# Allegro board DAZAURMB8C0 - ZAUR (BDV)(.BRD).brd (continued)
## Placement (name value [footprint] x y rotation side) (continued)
L5  **MS@HCB2012KF-220T60  [R0805]  209.61 28.18 0 top
L6  BLM15AG121SN1D  [R0402]  184.72 19.42 180 top
L7  BLM15AG121SN1D  [R0402]  184.72 18.27 0 top
L8  *MS@BLM15AG601SN1D  [R0402]  39.69 116.45 0 bottom
L9  *MS@BLM15AG601SN1D  [R0402]  39.61 115.25 0 bottom
L10  **MS@PBY160808T-600Y-N  [R0603]  195.69 24.09 90 bottom
L11  HCB1005KF-330T30  [R0402]  72.22 23.35 90 bottom
L12  HCB1005KF-330T30  [R0402]  75.5 23.99 90 bottom
L13  HCB1608KF-121T30  [R0603]  204.28 19.54 270 bottom
L14  PBY160808T-600Y-N  [R0603]  201.64 18.15 180 bottom
NOREF  -  [unnamed]  12.38 3.42 0 top
NOREF#2  -  [unnamed]  134.02 124.57 0 top
NOREF#3  -  [unnamed]  216.6 44.31 0 top
NOREF#4  -  [#2]  5.68 -31.69 0 top
NOREF#5  -  [#2]  138.82 46.03 0 top
NOREF#6  -  [#2]  165.2 -14.93 0 top
NOREF#7  -  [unnamed]  134.43 121.14 180 bottom
NOREF#8  -  [#2]  145.65 98.38 180 bottom
NOREF#9  -  [unnamed]  10.86 9 180 bottom
NOREF#10  -  [unnamed]  180.78 11.92 180 bottom
PC1  0.1u/25V_4  [C0402]  68.7 125.09 270 top
PC2  1u/10V_4  [C0402]  65.7 125.08 90 top
PC3  10u/10V_4  [C0402_2]  66.77 125.08 270 top
PC4  *22U/6.3V_6  [C0603]  60.86 124.64 90 top
PC5  22u/6.3V_6  [C0603]  61.99 122.62 0 top
PC6  10u/25V_6  [C0603]  69.87 122.24 270 top
PC7  10u/25V_6  [C0603]  71.29 122.14 270 top
PC8  10u/25V_6  [C0603]  72.59 124.61 0 top
PC9  *22U/6.3V_6  [C0603]  49.55 122.11 0 top
PC10  0.047u/50V_6  [C0603]  42.1 122.03 0 top
PC11  0.1u/25V_4  [C0402]  68.69 121.79 90 top
PC12  EV@330u/2V_7343H1.9  [CC7343]  87.25 120.67 180 top
PC13  2200P/50V_4  [C0402]  72.73 122.39 90 top
PC14  *EV@10u/25V_8  [C0805]  78.54 119.86 90 top
PC15  EV@10u/25V_8  [C0805]  80.51 119.86 90 top
PC16  0.1u/25V_4  [C0402]  59.95 119.73 0 top
PC17  EV@2200p/50V_4  [C0402]  76.1 119.54 90 top
PC18  EV@0.1u/25V_4  [C0402]  77.06 119.54 90 top
PC19  0.47u/10V_4  [C0402]  68.13 119.09 90 top
PC20  2200P/50V_4  [C0402]  12.41 118.43 90 top
PC21  10u/6.3V_4  [C0402_2]  64.35 118.27 180 top
PC22  *EV@22p/50V_4  [C0402]  87.44 117.33 90 top
PC23  *EV@0.1u/6.3V_2  [C0201]  90.1 116.32 90 top
PC24  *EV@2200p/50V_4  [C0402]  82.07 116.28 0 top
PC25  *EV@22u/6.3V_6  [C0603]  91.88 116.19 0 top
PC26  *EV@0.1u/6.3V_2  [C0201]  94.42 115.81 0 top
PC27  1000p/50V_4  [C0402]  42.35 115.4 180 top
PC28  *EV@10u/6.3V_4  [C0402_2]  84.64 113.65 90 top
PC29  *EV@0.01u/50V_4  [C0402]  85.79 113.65 90 top
PC30  *EV@2200p/50V_4  [C0402]  80.99 110.39 90 top
PC31  *EV@22u/6.3V_6  [C0603]  116.39 109.59 270 top
PC32  *EV@22u/6.3V_6  [C0603]  112.94 109.08 0 top
PC33  *EV@330u/2V_7343H1.9  [CC7343]  89.61 105.13 180 top
PC34  EV@0.1u/16V_4  [C0402]  96.33 101.84 90 top
PC35  EV@0.1u/16V_4  [C0402]  95.06 101.71 90 top
PC36  EV@22u/6.3V_6  [C0603]  92.26 101.33 90 top
PC37  EV@22u/6.3V_6  [C0603]  93.79 101.33 90 top
PC38  22u/6.3V_6  [C0603]  71.18 82.92 270 top
PC39  22u/6.3V_6  [C0603]  72.71 82.92 270 top
PC40  22u/6.3V_6  [C0603]  71.18 79.49 90 top
PC41  22u/6.3V_6  [C0603]  72.71 79.49 90 top
PC42  *330u/2V_7343H1.9  [CC7343]  134.79 75.68 0 top
PC43  EV@22u/6.3V_6  [C0603]  144.6 74.61 90 top
PC44  EV@22u/6.3V_6  [C0603]  146.02 74.61 90 top
PC45  EV@22u/6.3V_6  [C0603]  147.43 74.61 90 top
PC46  EV@22u/6.3V_6  [C0603]  148.84 74.61 90 top
PC47  EV@22u/6.3V_6  [C0603]  142.87 74.5 90 top
PC48  *EV@0.1u/25V_4  [C0402]  145.59 67.27 270 top
PC49  EV@2200p/50V_4  [C0402]  146.55 67.27 270 top
PC50  22u/6.3V_6  [C0603]  87.13 66 270 top
PC51  22u/6.3V_6  [C0603]  90.23 63.36 180 top
PC52  22u/6.3V_6  [C0603]  98.03 61.2 270 top
PC53  0.1u/25V_4  [C0402]  136.63 61.12 0 top
PC54  22u/6.3V_6  [C0603]  100.26 60.69 180 top
PC55  2200p/50V_4  [C0402]  136.62 60.15 0 top
PC56  *2200p/50V_4  [C0402]  133.06 59.58 90 top
PC57  22u/6.3V_6  [C0603]  101.28 58.66 270 top
PC58  22u/6.3V_6  [C0603]  103.95 58.15 180 top
PC59  22u/6.3V_6  [C0603]  98.23 58.03 90 top
PC60  82p/50V_4  [C0402]  145.81 57.95 180 top
PC61  0.1u/16V_4  [C0402]  147.53 57.95 180 top
PC62  22u/6.3V_6  [C0603]  101.66 56.63 180 top
PC63  22u/6.3V_6  [C0603]  104.71 56.63 180 top
PC64  22u/6.3V_6  [C0603]  98.11 55.71 180 top
PC65  0.1u/25V_4  [C0402]  141.07 55.35 0 top
PC66  22u/6.3V_6  [C0603]  101.15 54.72 180 top
PC67  2.2u/10V_4  [C0402]  150.97 54.63 0 top
PC68  2.2u/10V_4  [C0402]  141.07 54.39 180 top
PC69  2200p/50V_4  [C0402]  137.44 53.9 90 top
PC70  22u/6.3V_6  [C0603]  100.39 53.3 180 top
PC71  0.1u/25V_4  [C0402]  141.45 53.05 90 top
PC72  *330u/2V_7343H1.9  [CC7343]  132.13 52.49 0 top
PC73  0.1u/25V_4  [C0402]  141.42 51.32 90 top
PC74  0.1u/25V_4  [C0402]  138.97 49.66 0 top
PC75  0.1u/16V_4  [C0402]  149.2 49.61 270 top
PC76  82p/50V_4  [C0402]  146.13 49.5 180 top
PC77  0.1u/16V_4  [C0402]  147.85 49.23 0 top
PC78  0.1u/25V_4  [C0402]  138.65 40.78 270 top
PC79  2200p/50V_4  [C0402]  145.73 40.75 90 top
PC80  *0.1u/25V_4  [C0402]  146.69 40.75 90 top
PC81  10P/50V_4  [C0402]  145.88 36.09 90 top
PC82  0.1u/50V_4  [C0402]  132.37 33.92 90 top
PC83  0.1u/50V_4  [C0402]  133.33 33.92 270 top
PC84  100p/50V_4  [C0402]  138.49 33.92 180 top
PC85  *22U/6.3V_6  [C0603]  147.75 33.59 0 top
PC86  100p/50V_4  [C0402]  136.99 32.9 180 top
PC87  0.1u/16V_4  [C0402]  144.72 32.68 270 top
PC88  22u/6.3V_6  [C0603]  147.75 32.17 0 top
PC89  *100p/50V_4  [C0402]  136.99 31.94 180 top
PC90  0.1u/50V_4  [C0402]  125.36 31.46 180 top
PC91  10u/6.3V_6  [C0603]  21.14 30.97 180 top
PC92  4.7u/6.3V_4  [C0402_2]  196.28 30.97 270 top
PC93  0.1u/16V_4  [C0402]  18.86 30.85 0 top
PC94  22u/6.3V_6  [C0603]  147.75 30.76 0 top
PC95  2.2u/10V_4  [C0402]  131.99 30.58 90 top
PC96  2200P/50V_4  [C0402]  125.36 30.5 180 top
PC97  1u/25V_4  [C0402]  24.06 30.39 180 top
PC98  1u/25V_4  [C0402]  157.82 30.03 90 top
PC99  1u/25V_4  [C0402]  152.73 29.86 90 top
PC100  *0.1u/16V_4  [C0402]  24.73 29.2 180 top
PC101  *0.1u/16V_4  [C0402]  136.99 29.06 0 top
PC102  1000p/50V_4  [C0402]  18.48 28.82 0 top
PC103  0.01u/50V_4  [C0402]  134.08 28.56 90 top
PC104  10u/6.3V_4  [C0402_2]  43.24 28.31 270 top
PC105  0.01u/50V_4  [C0402]  44.38 28.46 270 top
PC106  10u/6.3V_6  [C0603]  151.54 28.27 270 top
PC107  0.1u/16V_4  [C0402]  24.73 28.23 180 top
PC108  *0.01u/50V_4  [C0402]  120.97 28.18 270 top
PC109  *22p/50V_4  [C0402]  192.72 28.33 0 top
PC110  22u/6.3V_6  [C0603]  32.95 28.05 270 top
PC111  22u/6.3V_6  [C0603]  34.48 28.05 270 top
PC112  0.1u/16V_4  [C0402]  152.72 27.82 270 top
PC113  0.1u/16V_4  [C0402]  157.34 27.8 270 top
PC114  1000p/50V_4  [C0402]  18.48 27.8 0 top
PC115  *0.1u/16V_4  [C0402]  24.73 27.27 180 top
PC116  1u/25V_4  [C0402]  24.95 26.28 180 top
PC117  0.1u/16V_4  [C0402]  19.49 26.02 90 top
PC118  0.47u/6.3V_4  [C0402]  192.44 25.97 180 top
PC119  10u/6.3V_6  [C0603]  18.27 26 90 top
PC120  *0.1u/6.3V_2  [C0201]  39.18 25.51 0 top
PC121  10u/6.3V_6  [C0603]  156.4 25.13 90 top
PC122  0.1u/6.3V_2  [C0201]  34.35 25.01 270 top
PC123  *22U/6.3V_6  [C0603]  32.95 24.88 90 top
PC124  *22p/50V_4  [C0402]  40.83 24.55 270 top
PC125  *2200p/50V_6  [C0603]  37.02 23.74 0 top
PC126  *47p/50V_4  [C0402]  101.79 21.76 0 top
PC127  *47p/50V_4  [C0402]  105.37 20.41 90 top
PC128  4.7u/10V_4  [C0402_2]  43.05 19.38 270 top
PC129  0.1u/16V_4  [C0402]  197.14 17.99 180 top
PC130  10u/6.3V_6  [C0603]  194.83 16.55 90 top
PC131  10u/6.3V_6  [C0603]  196.25 16.17 90 top
PC132  *1u/10V_4  [C0402]  68.69 125.11 90 bottom
PC133  *1u/10V_4  [C0402]  66.27 125.1 90 bottom
PC134  EV@0.1u/16V_4  [C0402]  91.63 124.83 270 bottom
PC135  22u/6.3V_6  [C0603]  52.08 124.35 270 bottom
PC136  22u/6.3V_6  [C0603]  55.35 124.09 270 bottom
PC137  22u/6.3V_6  [C0603]  56.85 124.08 270 bottom
PC138  22u/6.3V_6  [C0603]  53.91 124.07 270 bottom
PC139  *680p/50V_6  [C0603]  61.98 123.29 90 bottom
PC140  22u/6.3V_6  [C0603]  49.55 122.11 0 bottom
PC141  *EV@10p/50V_4  [C0402]  70.64 121.76 0 bottom
PC142  10u/6.3V_4  [C0402_2]  63.43 121.14 0 bottom
PC143  *10u/6.3V_4  [C0402_2]  64.58 119.87 180 bottom
PC144  0.1u/50V_4  [C0402]  39.69 120.15 0 bottom
PC145  *EV@10p/50V_4  [C0402]  70.93 119.84 0 bottom
PC146  EV@10u/25V_8  [C0805]  77.4 118.99 90 bottom
PC147  0.1u/50V_4  [C0402]  39.69 119.19 0 bottom
PC148  EV@0.1u/6.3V_2  [C0201]  72.32 118.55 270 bottom
PC149  *EV@1000p/50V_4  [C0402]  75.93 118.46 90 bottom
PC150  *EV@180p/25V_2  [C0201]  70.65 117.99 180 bottom
PC151  EV@150p/50V_4  [C0402]  74.59 117.77 0 bottom
PC152  EV@1u/6.3V_2  [C0201]  71.18 117.21 180 bottom
PC153  EV@0.1u/25V_4  [C0402]  76 116.43 270 bottom
PC154  EV@0.1u/6.3V_2  [C0201]  71.64 116.04 180 bottom
PC155  EV@82p/50V_4  [C0402]  74.66 115.85 0 bottom
PC156  EV@330u/2V_7343H1.9  [CC7343]  88.65 114.36 180 bottom
PC157  EV@2.2u/10V_4  [C0402]  66.49 114.18 180 bottom
PC158  EV@0.1u/25V_4  [C0402]  79.47 113.98 270 bottom
PC159  EV@0.1u/25V_4  [C0402]  77.55 113.86 270 bottom
PC160  *EV@10u/25V_8  [C0805]  81.57 113.74 180 bottom
PC161  *EV@100p/50V_4  [C0402]  67.28 113.22 0 bottom
PC162  EV@2.2u/10V_4  [C0402]  78.13 112.52 0 bottom
PC163  EV@0.47uF/6.3V_2  [C0201]  66.91 112.38 180 bottom
PC164  EV@10u/25V_8  [C0805]  81.57 111.76 180 bottom
PC165  *EV@100p/50V_4  [C0402]  67.28 111.3 0 bottom
PC166  EV@0.1u/25V_4  [C0402]  78.13 111.26 180 bottom
PC167  EV@0.1u/25V_4  [C0402]  76.4 107.57 0 bottom
PC168  EV@0.1u/16V_4  [C0402]  69.07 107.08 270 bottom
PC169  EV@0.1u/16V_4  [C0402]  70.99 107.08 90 bottom
PC170  *EV@82p/50V_4  [C0402]  74.15 107.05 270 bottom
PC171  EV@82p/50V_4  [C0402]  72.23 106.93 270 bottom
PC172  EV@150p/50V_4  [C0402]  75.03 104.98 0 bottom
PC173  EV@0.1u/6.3V_2  [C0201]  68.5 103.92 0 bottom
PC174  EV@15u/25V_7343H1.9  [CC7343]  70.52 98.69 270 bottom
PC175  *EV@2200p/50V_4  [C0402]  81.27 98.18 0 bottom
PC176  EV@10u/25V_8  [C0805]  78.75 97.7 180 bottom
PC177  EV@10u/25V_8  [C0805]  73.86 96.84 90 bottom
PC178  EV@2200p/50V_4  [C0402]  73.99 94.64 0 bottom
PC179  *EV@10u/25V_8  [C0805]  76.46 95.6 180 bottom
PC180  EV@0.1u/25V_4  [C0402]  73.99 93.68 0 bottom
PC181  EV@330u/2V_7343H1.9  [CC7343]  82.82 94.37 180 bottom
PC182  EV@2200p/50V_4  [C0402]  73.99 92.72 0 bottom
PC183  EV@10u/25V_8  [C0805]  76.46 93.63 180 bottom
PC184  *2200p/50V_4  [C0402]  68.9 89.14 0 bottom
PC185  EV@0.1u/16V_4  [C0402]  116.9 86.85 270 bottom
PC186  EV@10u/6.3V_6  [C0603]  118.17 85.1 270 bottom
PC187  EV@0.1u/16V_4  [C0402]  116.9 84.7 90 bottom
PC188  EV@0.1u/16V_4  [C0402]  104.33 84.19 90 bottom
PC189  *EV@10u/6.3V_4  [C0402_2]  105.47 84.19 90 bottom
PC190  EV@10u/6.3V_4  [C0402_2]  106.74 84.19 90 bottom
PC191  EV@1u/6.3V_4  [C0402]  117.16 83.3 180 bottom
PC192  EV@0.1u/16V_4  [C0402]  105.6 82.66 180 bottom
PC193  22u/6.3V_6  [C0603]  115.48 81.39 270 bottom
PC194  22u/6.3V_6  [C0603]  116.9 81.39 270 bottom
PC195  22u/6.3V_6  [C0603]  115.5 77.71 90 bottom
PC196  22u/6.3V_6  [C0603]  116.93 77.71 90 bottom
PC197  EV@0.1u/16V_4  [C0402]  149.11 77.66 180 bottom
PC198  EV@0.22u/10V_4  [C0402]  112.2 76.57 90 bottom
PC199  *EV@0.1u/16V_4  [C0402]  110.04 75.81 90 bottom
PC200  330u/2V_7343H1.9  [CC7343]  126.85 75.27 270 bottom
PC201  *EV@22u/6.3V_6  [C0603]  140.41 75.05 90 bottom
PC202  *EV@22u/6.3V_6  [C0603]  141.82 75.05 90 bottom
PC203  *2200p/50V_4  [C0402]  139.09 73.9 270 bottom
PC204  330u/2V_7343H1.9  [CC7343]  116.09 71.11 90 bottom
PC205  EV@0.1u/25V_4  [C0402]  149.09 69.6 180 bottom
PC206  10u/25V_8  [C0805]  125.9 68.83 270 bottom
PC207  *10u/25V_8  [C0805]  127.88 68.83 270 bottom
PC208  *EV@680p/50V_6  [C0603]  142.43 68.55 180 bottom
PC209  2200p/50V_4  [C0402]  123.48 68.51 270 bottom
PC210  0.1u/25V_4  [C0402]  124.44 68.51 270 bottom
PC211  EV@10u/25V_8  [C0805]  141.94 66.15 270 bottom
PC212  EV@10u/6.3V_6  [C0603]  149.52 65.06 270 bottom
PC213  330u/2V_7343H1.9  [CC7343]  118.26 63.87 180 bottom
PC214  10u/25V_8  [C0805]  134.34 63.77 180 bottom
PC215  EV@0.047u/6.3V_2  [C0201]  148.8 63.39 0 bottom
PC216  *10u/25V_8  [C0805]  139.86 63.23 270 bottom
PC217  *EV@0.01u/50V_4  [C0402]  142.03 63.1 180 bottom
PC218  *EV@1000p/50V_4  [C0402]  142.55 62.14 0 bottom
PC219  *EV@0.047u/6.3V_2  [C0201]  147.77 61.55 0 bottom
PC220  10u/25V_8  [C0805]  141.76 60.64 180 bottom
PC221  220p/50V_4  [C0402]  146.04 57.86 180 bottom
PC222  *1000p/25V_2  [C0201]  144.78 56.08 270 bottom
PC223  0.1u/25V_4  [C0402]  145.61 56.04 90 bottom
PC224  0.1u/6.3V_2  [C0201]  146.45 56.01 270 bottom
PC225  1u/6.3V_4  [C0402]  147.28 55.92 90 bottom
PC226  *10P/50V_4  [C0402]  148.24 55.92 270 bottom
PC227  *10P/50V_4  [C0402]  149.2 55.92 270 bottom
PC228  *10P/50V_4  [C0402]  150.16 55.92 270 bottom
PC229  10u/25V_8  [C0805]  138.54 55.78 0 bottom
PC230  *100p/50V_4  [C0402]  148.77 54.57 0 bottom
PC231  0.47uF/6.3V_2  [C0201]  148.35 52.78 180 bottom
PC232  *100p/50V_4  [C0402]  149.25 51.94 0 bottom
PC233  *82p/50V_4  [C0402]  146.96 51.72 0 bottom
PC234  0.1u/6.3V_2  [C0201]  148.55 51.1 0 bottom
PC235  330u/2V_7343H1.9  [CC7343]  123.81 50.67 270 bottom
PC236  10u/25V_8  [C0805]  143.53 49.94 180 bottom
PC237  *2200p/50V_4  [C0402]  137.79 48.45 180 bottom
PC238  10u/25V_8  [C0805]  140.26 48.4 0 bottom
PC239  *10u/25V_8  [C0805]  143.53 47.97 180 bottom
PC240  220p/50V_4  [C0402]  146.61 47.85 270 bottom
PC241  22u/6.3V_6  [C0603]  133.83 47.27 180 bottom
PC242  22u/6.3V_6  [C0603]  136.74 47.27 0 bottom
PC243  10u/6.3V_6  [C0603]  143.12 46.24 0 bottom
PC244  0.1u/25V_4  [C0402]  138.53 46.02 270 bottom
PC245  0.047u/6.3V_2  [C0201]  145.1 45.53 90 bottom
PC246  *0.047u/6.3V_2  [C0201]  146.87 44.69 90 bottom
PC247  *15u/25V_7343H1.9  [CC7343]  121.93 41.17 90 bottom
PC248  *1000p/50V_4  [C0402]  146.31 39.59 90 bottom
PC249  *0.01u/50V_4  [C0402]  145.33 39.58 270 bottom
PC250  10u/25V_8  [C0805]  142.28 38.96 0 bottom
PC251  0.1u/16V_4  [C0402]  130.5 38.6 90 bottom
PC252  *22u/6.3V_6  [C0603]  131.69 38.15 90 bottom
PC253  22u/6.3V_6  [C0603]  133.1 38.15 90 bottom
PC254  22u/6.3V_6  [C0603]  134.52 38.15 90 bottom
PC255  *22u/6.3V_6  [C0603]  135.93 38.15 90 bottom
PC256  22u/6.3V_6  [C0603]  137.34 38.15 90 bottom
PC257  22u/6.3V_6  [C0603]  150.36 37.8 270 bottom
PC258  22u/6.3V_6  [C0603]  151.77 37.8 270 bottom
PC259  *680p/50V_6  [C0603]  139.36 37.53 180 bottom
PC260  0.1u/16V_4  [C0402]  151.47 30.57 90 top
PC261  0.1u/16V_4  [C0402]  144.86 36.47 180 bottom
PC262  4.7u/6.3V_4  [C0402_2]  146.31 36.09 270 bottom
PC263  0.1u/25V_4  [C0402]  148.17 35.95 90 bottom
PC264  1u/10V_4  [C0402]  144.86 35.51 0 bottom
PC265  0.1u/50V_4  [C0402]  132.27 34.68 0 bottom
PC266  *22U/6.3V_6  [C0603]  157.52 34.64 270 bottom
PC267  1u/25V_4  [C0402]  130.31 33.77 0 bottom
PC268  10u/25V_8  [C0805]  126.03 33.92 90 bottom
PC269  2200P/50V_4  [C0402]  127.51 33.75 90 bottom
PC270  0.1u/16V_4  [C0402]  112.84 33.13 180 bottom
PC271  0.047u/50V_6  [C0603]  129.52 32.55 0 bottom
PC272  10u/25V_8  [C0805]  140.76 32.04 0 bottom
PC273  0.1u/25V_4  [C0402]  140.44 30.58 180 bottom
PC274  *680p/50V_6  [C0603]  144.72 30.08 0 bottom
PC275  2200P/50V_4  [C0402]  140.44 29.62 180 bottom
PC276  10u/25V_8  [C0805]  142.29 29.45 90 bottom
PC277  *680p/50V_6  [C0603]  127.29 29.23 270 bottom
PC278  0.1u/25V_4  [C0402]  130.38 28.99 180 bottom
PC279  *0.1u/16V_4  [C0402]  153.58 28.91 0 bottom
PC280  *0.1u/16V_4  [C0402]  156.26 28.91 180 bottom
PC281  0.1u/16V_4  [C0402]  154.92 28.53 90 bottom
PC282  0.1u/25V_4  [C0402]  128.77 28.16 270 bottom
PC283  1000p/50V_4  [C0402]  153.58 27.8 0 bottom
PC284  1000p/50V_4  [C0402]  156.26 27.8 180 bottom
PC285  0.1u/25V_4  [C0402]  130.38 27.78 180 bottom
PC286  0.1u/16V_4  [C0402]  32.19 24.98 90 bottom
PC287  22u/25V_8  [C0805]  109.19 24.23 90 bottom
PC288  0.1u/50V_4  [C0402]  105.78 23.52 270 bottom
PC289  *100p/50V_4  [C0402]  106.74 23.52 90 bottom
PC290  2200P/50V_4  [C0402]  107.7 23.52 90 bottom
PC291  22u/25V_8  [C0805]  111.31 22.85 90 bottom
PC292  22u/6.3V_6  [C0603]  31.97 22.79 270 bottom
PC293  *680p/50V_6  [C0603]  44.56 22.32 180 bottom
PC294  10u/25V_8  [C0805]  47.29 21.42 270 bottom
PC295  10u/25V_8  [C0805]  49.46 19.01 270 bottom
PC296  0.1u/25V_4  [C0402]  46.84 18.94 270 bottom
PC297  0.1u/25V_4  [C0402]  47.8 18.94 90 bottom
PC298  0.1u/16V_4  [C0402]  46.66 17.35 0 bottom
PC299  0.1u/25V_4  [C0402]  41.49 16.67 0 bottom
PC300  *22U/6.3V_6  [C0603]  28.56 15.82 90 bottom
PC301  22u/6.3V_6  [C0603]  29.97 15.82 90 bottom
PC302  22u/6.3V_6  [C0603]  31.38 15.82 90 bottom
PC303  22u/6.3V_6  [C0603]  32.79 15.82 90 bottom
PC304  1u/10V_4  [C0402]  43.73 15.8 90 bottom
PC305  2200P/50V_4  [C0402]  47.39 15.69 90 bottom
PC306  0.1u/16V_4  [C0402]  46.43 15.46 90 bottom
PC307  10P/50V_4  [C0402]  45.09 15.08 0 bottom
PC308  *22U/6.3V_6  [C0603]  35.88 15.02 0 bottom
PD1  P4SMAFJ20A  [D-3_8X2_5]  16.06 115.3 180 top
PD2  BAT54CW  [SOT23-1_7-65-3P]  127.22 33.46 270 top
PD3  PDZ5.6B  [D-SOD323-1_7X1_25-PMEG4005AEA]  107.6 21.1 0 top
PD4  PDZ5.6B  [D-SOD323-1_7X1_25-PMEG4005AEA]  104.41 22.52 180 top
PJ3  *short3720  [SHORT3720]  144.03 78.35 0 top
PJ6  *short3720  [SHORT3720]  154.61 32.76 180 top
PJ7  *short3720  [SHORT3720]  30.29 26.53 90 top
PJ8  *short3720  [SHORT3720]  45.78 25.44 270 top
PJ11  30706-00042-001  [DCJK-30706-00042-001-3P-SMT]  1.85 116.6 90 bottom
PJ15  *short3720  [SHORT3720]  128.1 45.96 270 bottom
PJ17  *short3720  [SHORT3720]  30.65 19.29 270 bottom
PJ18  50458-00801-V02  [WTB-50458-00801-V02-8P-L]  102.45 16.42 180 bottom
PL1  4.7uH/1.08A_2.5x2.0x1.2  [L2_5X2-1_2]  63.26 124.65 180 top
PL2  0.68uH/15.5A_7x7x3  [L6_6X6_6-2_8H]  55.54 122.39 180 top
PL3  *EV@1uH/3.35A_2.5x2.0x1.2  [L2_5X2-1_2H]  92.01 113.91 0 top
PL4  1uH/3.35A_2.5x2.0x1.2  [L2_5X2-1_2H]  36.84 27.42 180 top
PL5  2.2uH/1.67A_2.5x2.0x1.2  [L2_5X2-1_2H]  194.88 23.61 270 top
PL6  EV@1uH/11A_7x7x3  [L6_6X6_6-2_8H]  88.45 120.28 0 bottom
PL7  EV@0.22uH/23A_7x7x3  [L6_6X6_6-2_8H]  89.79 108.45 0 bottom
PL8  EV@0.22uH/23A_7x7x3  [L6_6X6_6-2_8H]  88.31 101.26 0 bottom
PL9  0.15uH/22A_7x7x3  [L6_6X6_6-2_8H]  133.81 75.17 180 bottom
PL10  EV@1uH/11A_7x7x3  [L6_6X6_6-2_8H]  146.08 73.63 90 bottom
PL11  0.15uH/22A_7x7x3  [L6_6X6_6-2_8H]  127.61 60.01 180 bottom
PL12  0.15uH/22A_7x7x3  [L6_6X6_6-2_8H]  130.76 52.83 180 bottom
PL13  1uH/11A_7x7x3  [L6_6X6_6-2_8H]  134.5 43.01 180 bottom
PL14  1uH/11A_7x7x3  [L6_6X6_6-2_8H]  152.2 32.94 0 bottom
PL15  6.8uH/4.5A_7x7x3  [L6_6X6_6-2_8H]  117.65 29.96 180 bottom
PL16  1uH/11A_7x7x3  [L6_6X6_6-2_8H]  37.05 19.3 180 bottom
PQ1  AONS32306  [POWER-5_67X4_8-1_27-5P]  39.3 118.6 0 top
PQ2  EV@2N7002K  [SOT23-2-95-3P]  130.87 118.35 90 top
PQ3  AONS32306  [POWER-5_67X4_8-1_27-5P]  47.15 117.97 180 top
PQ4  EV@2N7002K  [SOT23-2-95-3P]  144.84 71.49 270 top
PQ5  EV@2N7002K  [SOT23-2-95-3P]  148.27 69.07 0 top
PQ6  2N7002K  [SOT23-2-95-3P]  132.27 39.86 0 top
PQ7  2N7002KW  [SOT23-1_7-65-3P]  139.17 35.82 180 top
PQ8  AOSS32334C  [SOT23-2_38-95-3P]  26.25 33.01 90 top
PQ9  AONS32306  [POWER-5_2X5_55-1_27-5P]  117.61 31.48 270 top
PQ10  2N7002K  [SOT23-2-95-3P]  142.48 31.14 270 top
PQ11  2N7002K  [SOT23-2-95-3P]  47.48 16.07 90 top
PQ12  EV@2N7002K  [SOT23-2-95-3P]  137.09 122.92 90 bottom
PQ13  EV@2N7002K  [SOT23-2-95-3P]  131.63 122.16 90 bottom
PQ14  EV@AONY36354  [POWER-5X6-1_27-7P-0_8H]  81.09 119.19 0 bottom
PQ15  EV@2N7002K  [SOT23-2-95-3P]  129.6 118.35 90 bottom
PQ16  EV@AOE6932  [POWER-5X6-1_27-10P]  81.93 108.08 90 bottom
PQ17  EV@AOE6932  [POWER-5X6-1_27-10P]  80.37 101.41 90 bottom
PQ18  EV@2N7002K  [SOT23-2-95-3P]  94.04 91.68 180 bottom
PQ19  *2N7002K  [SOT23-2-95-3P]  62.28 90.41 0 bottom
PQ20  2N7002K  [SOT23-2-95-3P]  77.76 89.42 90 bottom
PQ21  DDTC144EUA-7-F  [SOT23-1_7-65-3P]  73.04 89.14 0 bottom
PQ22  EV@2N7002K  [SOT23-2-95-3P]  92.14 88.38 270 bottom
PQ23  2N7002K  [SOT23-2-95-3P]  62.31 86.85 180 bottom
PQ24  2N7002K  [SOT23-2-95-3P]  67.64 86.85 180 bottom
PQ25  2N7002K  [SOT23-2-95-3P]  71.94 84.95 90 bottom
PQ26  AOSS32334C  [SOT23-2_38-95-3P]  67.45 83.23 0 bottom
PQ27  EV@AO3413  [SOT23-2_38-95-3P]  105.19 80.25 270 bottom
PQ28  EV@2N7002K  [SOT23-2-95-3P]  108.77 79.49 270 bottom
PQ29  EV@2N7002K  [SOT23-2-95-3P]  112.38 79.11 270 bottom
PQ30  AONS36312  [POWER-5_2X5_55-1_27-5P]  137.65 68.23 270 bottom
PQ31  AONS36380  [POWER-5_2X5_55-1_27-5P]  132.04 68.21 90 bottom
PQ32  AOE6932  [POWER-5X6-1_27-10P]  135.48 59.46 270 bottom
PQ33  AOE6932  [POWER-5X6-1_27-10P]  138.62 52.09 270 bottom
PQ34  AONS32306  [POWER-5_2X5_55-1_27-5P]  127.08 40.42 270 bottom
PQ35  AONR32320C  [POWER-3X3-65-5P-ADNR21357]  123 34.28 270 bottom
PQ36  AONR32320C  [POWER-3X3-65-5P-ADNR21357]  124.32 30.21 0 bottom
PR1  *short_4  [S0402]  70.04 124.83 180 top
PR2  EV@1M_5%_6  [R0603]  133.69 121.53 90 top
PR3  EV@1M_5%_6  [R0603]  135.11 121.53 270 top
PR4  5.1_1%_6  [R0603]  62.12 120.06 180 top
PR5  *short_2  [S0201]  65.97 118.6 270 top
PR6  10_1%_2  [R0201]  66.73 118.65 90 top
PR7  *short_6  [S0603]  62.16 118.63 180 top
PR8  *short_4  [S0402]  69.15 118.22 90 top
PR9  EV@22_5%_8  [R0805]  127.19 118.22 90 top
PR10  *Short_0201  [S0201]  88.45 117.84 0 top
PR11  *EV@2.2_5%_6  [R0603]  82.87 117.59 0 top
PR12  49.9_1%_2  [R0201]  66.74 117.46 270 top
PR13  *EV@20K_1%_4  [R0402]  85.41 117.33 270 top
PR14  *EV@11.8K_1%_4  [R0402]  86.42 117.33 90 top
PR15  EV@100_1%_2  [R0201]  71.82 117.08 180 top
PR16  0.01_1%_0612  [RC3216]  52.97 116.9 90 top
PR17  *EV@0_5%_4  [R0402]  89.09 116.57 270 top
PR18  *short_2  [S0201]  69.53 116.45 180 top
PR19  *EV@100K_1%_2  [R0201]  84.52 115.3 90 top
PR20  *EV@0_5%_2  [R0201]  85.28 115.3 270 top
PR21  *short_2  [S0201]  52.67 114.45 270 top
PR22  *short_2  [S0201]  53.38 114.45 270 top
PR23  *EV@2.2_5%_6  [R0603]  82.78 110.87 0 top
PR24  *short_2  [S0201]  70.65 109.21 90 top
PR25  EV@22_5%_8  [R0805]  95.64 93.33 0 top
PR26  EV@22_5%_8  [R0805]  148.27 72 0 top
PR27  EV@1M_5%_6  [R0603]  142.17 71.11 270 top
PR28  EV@1M_5%_6  [R0603]  142.17 69.07 180 top
PR29  *short_4  [S0402]  149.29 65.65 270 top
PR30  *short_2  [S0201]  146.31 59.9 270 top
PR31  3.74K_1%_4  [R0402]  147.53 59.87 180 top
PR32  *short_2  [S0201]  148.74 59.53 90 top
PR33  *2.2_5%_6  [R0603]  131.86 59.25 270 top
PR34  24.9K_1%_4  [R0402]  145.81 58.91 180 top
PR35  1.43K_1%_4  [R0402]  147.53 58.91 180 top
PR36  *short_4  [S0402]  144.47 58.56 90 top
PR37  *short_2  [S0201]  148.96 57.54 270 top
PR38  *short_2  [S0201]  150.54 57.21 180 top
PR39  1_5%_6  [R0603]  141.52 56.54 180 top
PR40  *short_2  [S0201]  150.54 56.47 180 top
PR41  *short_6  [S0603]  139.5 55.93 90 top
PR42  *short_2  [S0201]  150.4 55.6 270 top
PR43  4.7_5%_4  [R0402]  150.71 53.63 0 top
PR44  19.1K_1%_4  [R0402]  150.94 52.57 0 top
PR45  237K_1%_4  [R0402]  152.66 52.57 0 top
PR46  *short_6  [S0603]  140.23 52.41 270 top
PR47  14K_1%_4  [R0402]  150.94 51.61 180 top
PR48  10K_1%_4  [R0402]  152.66 51.61 180 top
PR49  4.53K_1%_4  [R0402]  150.94 50.65 0 top
PR50  590_1%_4  [R0402]  152.66 50.65 0 top
PR51  *short_4  [S0402]  140.05 50.62 180 top
PR52  *short_2  [S0201]  137.37 49.87 0 top
PR53  *short_2  [S0201]  154.02 49.93 180 top
PR54  *short_6  [S0603]  142.23 49.76 0 top
PR55  28K_1%_4  [R0402]  150.94 49.69 0 top
PR56  1.47K_1%_4  [R0402]  152.66 49.69 0 top
PR57  10K_1%_2  [R0201]  137.38 49.13 180 top
PR58  22_5%_8  [R0805]  129.6 38.39 270 top
PR59  1K_1%_4  [R0402]  146.29 37.58 0 top
PR60  1M_5%_6  [R0603]  132.41 37.36 180 top
PR61  *10K_1%_4  [R0402]  147.64 36.31 90 top
PR62  *1K_1%_4  [R0402]  144.92 36.09 270 top
PR63  *short_6  [S0603]  149.46 36.05 0 top
PR64  100K_1%_2  [R0201]  143.7 35.55 270 top
PR65  100K_1%_4  [R0402]  134.09 35.27 180 top
PR66  10K_1%_4  [R0402]  145.3 34.75 180 top
PR67  1M_5%_6  [R0603]  136.44 34.69 90 top
PR68  10K_1%_2  [R0201]  142.68 34.02 0 top
PR69  100K_1%_4  [R0402]  134.29 33.92 90 top
PR70  137K_1%_4  [R0402]  135.25 33.92 270 top
PR71  *short_2  [S0201]  144.74 33.9 180 top
PR72  *short_2  [S0201]  142.68 33.26 0 top
PR73  10K_1%_4  [R0402]  143.76 33.2 270 top
PR74  20_5%_12  [R1206]  129.64 32.03 270 top
PR75  100K_1%_2  [R0201]  195.26 31.61 270 top
PR76  *short_6  [S0603]  197.67 31.36 90 top
PR77  *20.5K_1%_4  [R0402]  136.99 30.98 0 top
PR78  15K_1%_2  [R0201]  193.99 30.72 90 top
PR79  *short_2  [S0201]  195.13 30.72 0 top
PR80  100K_5%_4  [R0402]  136.99 30.02 0 top
PR81  *short_2  [S0201]  138.49 29.83 0 top
PR82  22.6K_1%_4  [R0402]  192.72 29.32 180 top
PR83  *short_2  [S0201]  26.6 29.2 0 top
PR84  *100K_1%_2  [R0201]  138.36 29.04 180 top
PR85  4.02K_1%_4  [R0402]  131.08 29.01 180 top
PR86  *100K_1%_2  [R0201]  140.02 28.94 90 top
PR87  *0_5%_2  [R0201]  140.78 28.94 270 top
PR88  *short_2  [S0201]  141.54 28.94 90 top
PR89  100K_1%_4  [R0402]  133.12 28.56 270 top
PR90  *short_2  [S0201]  26.6 28.18 180 top
PR91  316K_1%_4  [R0402]  135.5 28.08 180 top
PR92  10_1%_6  [R0603]  130.95 27.52 180 top
PR93  *short_2  [S0201]  26.6 27.29 180 top
PR94  *short_2  [S0201]  42.99 26.91 0 top
PR95  *short_8  [S0805]  149.16 26.91 0 top
PR96  100K_1%_2  [R0201]  42.99 26.15 180 top
PR97  *short_8  [S0805]  153.99 25.77 180 top
PR98  *2.2_5%_6  [R0603]  37.02 25.26 0 top
PR99  *Short_0201  [S0201]  35.11 25.01 90 top
PR100  20K_1%_2  [R0201]  41.84 24.55 90 top
PR101  10K_1%_4  [R0402]  42.86 24.8 270 top
PR102  *short_4  [S0402]  192.47 24.75 180 top
PR103  *short_4  [S0402]  39.43 24.62 180 top
PR104  *Short_0201  [S0201]  192.97 23.35 270 top
PR105  *0_5%_2  [R0201]  100.14 21.58 0 top
PR106  100_5%_2  [R0201]  104.33 20.94 270 top
PR107  100_5%_2  [R0201]  103.34 21.22 180 top
PR108  100_5%_2  [R0201]  101.53 19.29 270 top
PR109  *short_6  [S0603]  45.09 18.65 0 top
PR110  1M_5%_2  [R0201]  102.42 18.4 0 top
PR111  *short_2  [S0201]  47.69 18.15 180 top
PR112  *0_5%_2  [R0201]  49.85 16.88 0 top
PR113  10K_1%_4  [R0402]  44.4 16.62 270 top
PR114  *short_2  [S0201]  49.85 16.12 180 top
PR115  *100K_1%_2  [R0201]  45.36 15.91 270 top
PR116  *Short_0201  [S0201]  63.81 125.59 0 bottom
PR117  *short_2  [S0201]  88.77 125.33 90 bottom
PR118  EV@60.4K_1%_4  [R0402]  89.99 125.32 180 bottom
PR119  *short_4  [S0402]  135.7 125.08 180 bottom
PR120  *short_2  [S0201]  67.11 124.8 270 bottom
PR121  *0_5%_2  [R0201]  67.82 124.8 270 bottom
PR122  *short_2  [S0201]  69.67 125 180 bottom
PR123  EV@100K_NTC_4_1%  [R0402]  89.99 124.36 180 bottom
PR124  EV@100K_NTC_4_1%  [R0402]  88.08 124.35 0 bottom
PR125  *short_8  [S0805]  58.77 123.78 90 bottom
PR126  *4.7_5%_6  [R0603]  60.57 123.29 270 bottom
PR127  *EV@10K_1%_4  [R0402]  71.2 122.72 0 bottom
PR128  *EV@0_5%_4  [R0402]  74.74 122.54 0 bottom
PR129  EV@22_5%_8  [R0805]  128.84 122.16 90 bottom
PR130  EV@1_5%_6  [R0603]  77.07 121.93 180 bottom
PR131  EV@2.2_5%_6  [R0603]  73.1 121.84 90 bottom
PR132  *short_6  [S0603]  65.01 121.78 270 bottom
PR133  100K_1%_2  [R0201]  66.23 121.27 0 bottom
PR134  *short_2  [S0201]  67.24 121.27 0 bottom
PR135  *short_4  [S0402]  74.31 121.14 270 bottom
PR136  *EV@10K_1%_4  [R0402]  70.93 120.8 180 bottom
PR137  *short_4  [S0402]  69.59 120.42 270 bottom
PR138  EV@7.32K_1%_4  [R0402]  66.49 119.99 0 bottom
PR139  *107K_1%_4  [R0402]  74.59 119.69 180 bottom
PR140  *short_2  [S0201]  73.21 119.67 180 bottom
PR141  EV@22_5%_8  [R0805]  126.81 119.62 90 bottom
PR142  *short_2  [S0201]  72.32 119.54 90 bottom
PR143  EV@13.3K_1%_4  [R0402]  68.34 119.44 270 bottom
PR144  EV@13K_1%_4  [R0402]  66.49 119.03 0 bottom
PR145  EV@10K_1%_4  [R0402]  70.93 118.88 0 bottom
PR146  EV@10K_1%_4  [R0402]  74.59 118.73 0 bottom
PR147  EV@9.53K_1%_4  [R0402]  73.25 118.43 90 bottom
PR148  EV@10K_1%_4  [R0402]  69.59 118.3 90 bottom
PR149  EV@237K_1%_4  [R0402]  66.49 118.02 180 bottom
PR150  EV@19.1K_1%_4  [R0402]  68.21 118.02 180 bottom
PR151  EV@1.69K_1%_4  [R0402]  72.58 117.08 0 bottom
PR152  EV@6.04K_1%_4  [R0402]  66.49 117.06 180 bottom
PR153  EV@60.4K_1%_4  [R0402]  68.21 117.06 180 bottom
PR154  EV@60.4K_1%_4  [R0402]  74.66 116.81 0 bottom
PR155  *short_2  [S0201]  69.93 116.38 270 bottom
PR156  EV@11K_1%_4  [R0402]  66.49 116.1 180 bottom
PR157  EV@22.6K_1%_4  [R0402]  68.21 116.1 0 bottom
PR158  *short_6  [S0603]  77.38 116.07 90 bottom
PR159  *short_2  [S0201]  70.64 115.87 270 bottom
PR160  *EV@10K_1%_2  [R0201]  72.55 115.71 270 bottom
PR161  *EV@10K_1%_2  [R0201]  73.32 115.71 270 bottom
PR162  *short_2  [S0201]  71.64 115.33 180 bottom
PR163  *short_2  [S0201]  69.66 115.3 270 bottom
PR164  EV@10K_1%_4  [R0402]  66.49 115.14 0 bottom
PR165  EV@14K_1%_4  [R0402]  68.21 115.14 0 bottom
PR166  EV@4.7_5%_4  [R0402]  68.21 114.18 0 bottom
PR167  *short_4  [S0402]  78.51 113.86 270 bottom
PR168  *short_2  [S0201]  69.66 113.52 0 bottom
PR169  EV@3.9_1%_4  [R0402]  68.27 112.26 0 bottom
PR170  EV@4.7_5%_4  [R0402]  79.47 111.64 270 bottom
PR171  EV@1K_1%_4  [R0402]  69.05 111.3 0 bottom
PR172  EV@140_1%_4  [R0402]  67.28 110.34 180 bottom
PR173  EV@18.2K_1%_4  [R0402]  69.05 110.34 180 bottom
PR174  *short_6  [S0603]  77.96 109.47 270 bottom
PR175  EV@487_1%_4  [R0402]  67.28 109.38 180 bottom
PR176  EV@105K_1%_4  [R0402]  69.05 109.38 180 bottom
PR177  EV@17.4K_1%_4  [R0402]  67.28 108.42 180 bottom
PR178  EV@11K_1%_4  [R0402]  69.05 108.42 0 bottom
PR179  *short_2  [S0201]  75.02 107.58 90 bottom
PR180  EV@6.65K_1%_4  [R0402]  67.15 107.08 270 bottom
PR181  EV@1.4K_1%_4  [R0402]  68.11 107.08 270 bottom
PR182  *EV@1K_1%_4  [R0402]  70.03 107.08 90 bottom
PR183  EV@56.2K_1%_4  [R0402]  73.19 106.93 270 bottom
PR184  *short_2  [S0201]  65.72 106.92 270 bottom
PR185  EV@1_5%_6  [R0603]  77.96 106.85 90 bottom
PR186  *short_6  [S0603]  75.95 106.38 180 bottom
PR187  *EV@1K_1%_4  [R0402]  65.81 105.88 180 bottom
PR188  *short_2  [S0201]  67.25 105.85 180 bottom
PR189  EV@1_1%_4  [R0402]  68.89 105.74 0 bottom
PR190  EV@1.4K_1%_4  [R0402]  70.61 105.74 0 bottom
PR191  EV@10K_1%_4  [R0402]  72.33 105.21 90 bottom
PR192  *short_4  [S0402]  73.29 105.21 90 bottom
PR193  EV@10K_1%_2  [R0201]  76.9 105.14 180 bottom
PR194  EV@1_1%_4  [R0402]  68.89 104.78 0 bottom
PR195  EV@6.65K_1%_4  [R0402]  70.61 104.78 0 bottom
PR196  *short_2  [S0201]  69.51 103.94 0 bottom
PR197  *short_2  [S0201]  70.93 103.92 0 bottom
PR198  EV@1_5%_6  [R0603]  75.8 99.27 180 bottom
PR199  *EV@2.2_5%_6  [R0603]  83.44 97.98 0 bottom
PR200  EV@100K_NTC_4_1%  [R0402]  86.74 97.23 0 bottom
PR201  EV@100K_NTC_4_1%  [R0402]  88.46 97.23 0 bottom
PR202  *short_2  [S0201]  89.67 97.22 270 bottom
PR203  EV@60.4K_1%_4  [R0402]  88.46 96.27 0 bottom
PR204  *220_5%_8  [R0805]  61.28 93.84 90 bottom
PR205  *100K_1%_6  [R0603]  71.31 92.06 270 bottom
PR206  EV@100_1%_2  [R0201]  85.61 91.5 180 bottom
PR207  EV@100_1%_2  [R0201]  81.82 91.5 180 bottom
PR208  *short_2  [S0201]  84.24 91.49 180 bottom
PR209  *short_2  [S0201]  83.21 91.49 0 bottom
PR210  1M_5%_6  [R0603]  75.27 89.19 270 bottom
PR211  1M_5%_6  [R0603]  69.02 91.05 90 bottom
PR212  1M_5%_6  [R0603]  70.8 89.14 90 bottom
PR213  22_5%_8  [R0805]  81.34 89.14 0 bottom
PR214  EV@1M_5%_6  [R0603]  88.07 88.63 270 bottom
PR215  EV@1M_5%_6  [R0603]  89.6 88.63 90 bottom
PR216  *short_4  [S0402]  115 88.51 180 bottom
PR217  EV@100K_1%_4  [R0402]  116.77 88.51 180 bottom
PR218  *short_4  [S0402]  118.17 88.38 90 bottom
PR219  22_5%_8  [R0805]  64.96 87.74 90 bottom
PR220  EV@10K_1%_4  [R0402]  106.49 87.49 0 bottom
PR221  *short_4  [S0402]  96.07 87.36 0 bottom
PR222  *EV@0_5%_4  [R0402]  118.43 86.98 0 bottom
PR223  EV@12.7K_1%_4  [R0402]  106.49 86.47 0 bottom
PR224  *short_8  [S0805]  103.69 86.09 0 bottom
PR225  *short_8  [S0805]  119.9 84.34 90 bottom
PR226  22_5%_8  [R0805]  71.06 82.28 180 bottom
PR227  EV@1M_5%_6  [R0603]  110.81 81.52 180 bottom
PR228  EV@1M_5%_6  [R0603]  113.45 81.52 180 bottom
PR229  *short_2  [S0201]  130.49 81.39 180 bottom
PR230  *short_2  [S0201]  123.28 80.62 180 bottom
PR231  60.4K_1%_4  [R0402]  132.81 80.16 0 bottom
PR232  100_1%_2  [R0201]  129.73 80.02 90 bottom
PR233  *short_2  [S0201]  134.02 79.21 90 bottom
PR234  100K_NTC_4_1%  [R0402]  131.09 79.2 0 bottom
PR235  100K_NTC_4_1%  [R0402]  132.81 79.2 0 bottom
PR236  *short_4  [S0402]  113.22 76.57 270 bottom
PR237  EV@100K_1%_4  [R0402]  111.06 75.81 270 bottom
PR238  *EV@10K_1%_4  [R0402]  112.08 74.66 90 bottom
PR239  EV@20K_1%_2  [R0201]  113.09 74.66 270 bottom
PR240  *EV@100K_1%_6  [R0603]  110.81 73.52 90 bottom
PR241  *2.2_5%_6  [R0603]  138.67 72.31 180 bottom
PR242  *EV@4.7_5%_6  [R0603]  141.82 70.57 90 bottom
PR243  EV@2.2_5%_6  [R0603]  149.25 67.81 90 bottom
PR244  EV@105K_1%_4  [R0402]  142.03 64.06 0 bottom
PR245  EV@10_5%_4  [R0402]  149.77 62.73 270 bottom
PR246  EV@100K_1%_2  [R0201]  148.69 62.54 270 bottom
PR247  *short_2  [S0201]  147.84 62.27 180 bottom
PR248  *short_2  [S0201]  146.77 61.96 0 bottom
PR249  EV@6.49K_1%_4  [R0402]  143.89 61.76 270 bottom
PR250  EV@9.31K_1%_2  [R0201]  144.84 62.09 270 bottom
PR251  *short_4  [S0402]  145.79 61.76 90 bottom
PR252  *EV@0_5%_2  [R0201]  146.78 61.2 180 bottom
PR253  *short_4  [S0402]  149.12 60.9 0 bottom
PR254  1_5%_6  [R0603]  139.45 60.31 270 bottom
PR255  10K_1%_4  [R0402]  146.04 58.82 180 bottom
PR256  2.2_5%_6  [R0603]  147.61 58.76 90 bottom
PR257  4.7_5%_4  [R0402]  144.69 58.07 90 bottom
PR258  *10K_1%_2  [R0201]  151.06 56.63 270 bottom
PR259  10.5K_1%_4  [R0402]  150.97 54.58 0 bottom
PR260  16.5K_1%_4  [R0402]  150.72 53.62 180 bottom
PR261  3.9_1%_4  [R0402]  148.64 53.61 0 bottom
PR262  10K_1%_4  [R0402]  152.33 53.58 270 bottom
PR263  100_1%_2  [R0201]  120.71 52.95 270 bottom
PR264  9.09K_1%_4  [R0402]  150.97 52.66 180 bottom
PR265  *short_2  [S0201]  119.57 52.44 180 bottom
PR266  1_5%_6  [R0603]  142.94 52.35 270 bottom
PR267  22.6K_1%_4  [R0402]  152.72 52.23 180 bottom
PR268  1K_1%_4  [R0402]  150.97 51.7 0 bottom
PR269  EV@100_1%_2  [R0201]  145.62 51.36 90 bottom
PR270  11K_1%_4  [R0402]  152.82 51.27 0 bottom
PR271  *short_2  [S0201]  120.71 50.91 180 bottom
PR272  *short_4  [S0402]  147.09 50.76 0 bottom
PR273  60.4K_1%_4  [R0402]  151.17 50.36 270 bottom
PR274  16.2K_1%_4  [R0402]  152.97 50.3 180 bottom
PR275  1_1%_4  [R0402]  149.83 50.26 180 bottom
PR276  54.9K_1%_4  [R0402]  144.41 49.49 0 top
PR277  6.04K_1%_4  [R0402]  152.97 49.34 0 bottom
PR278  1.43K_1%_4  [R0402]  147.8 49.3 0 bottom
PR279  1.43K_1%_4  [R0402]  149.52 49.3 180 bottom
PR280  3.74K_1%_4  [R0402]  151.24 48.91 180 bottom
PR281  60.4K_1%_4  [R0402]  127.02 48.79 180 bottom
PR282  100K_NTC_4_1%  [R0402]  128.74 48.79 0 bottom
PR283  100K_NTC_4_1%  [R0402]  131.43 48.78 0 bottom
PR284  *short_2  [S0201]  129.96 48.78 270 bottom
PR285  *2.2_5%_6  [R0603]  135.62 48.68 180 bottom
PR286  1_1%_4  [R0402]  148.39 47.95 180 bottom
PR287  *1K_1%_4  [R0402]  150.11 47.95 0 bottom
PR288  *short_2  [S0201]  151.34 47.92 270 bottom
PR289  10K_1%_4  [R0402]  145.65 47.85 270 bottom
PR290  *short_2  [S0201]  150.46 47.11 0 bottom
PR291  3.74K_1%_4  [R0402]  148.5 46.61 90 bottom
PR292  *1K_1%_4  [R0402]  149.46 46.61 90 bottom
PR293  10_5%_4  [R0402]  145.29 46.5 0 bottom
PR294  2.2_5%_6  [R0603]  140.32 46.24 180 bottom
PR295  *short_2  [S0201]  150.32 45.82 270 bottom
PR296  100K_1%_2  [R0201]  145.95 45.55 0 bottom
PR297  *short_2  [S0201]  148.4 45.2 270 bottom
PR298  *short_2  [S0201]  146.14 44.69 270 bottom
PR299  *short_4  [S0402]  148.52 44.18 0 bottom
PR300  *short_2  [S0201]  146.52 43.65 90 bottom
PR301  *0_5%_2  [R0201]  147.25 43.65 270 bottom
PR302  *short_4  [S0402]  147.02 42.65 180 bottom
PR303  *0_5%_2  [R0201]  149.16 41.77 0 bottom
PR304  20K_1%_2  [R0201]  147.65 41.69 0 bottom
PR305  SP@5.1K_1%_4  [R0402]  146.31 41.31 270 bottom
PR306  *short_2  [S0201]  147.98 39.76 270 bottom
PR307  *4.7_5%_6  [R0603]  138.75 39.55 90 bottom
PR308  73.2K_1%_4  [R0402]  144.37 39.08 90 bottom
PR309  *Short_0201  [S0201]  150.33 39.61 0 bottom
PR310  *short_2  [S0201]  115 38.59 90 bottom
PR311  32.4K_1%_4  [R0402]  112.58 38.57 180 bottom
PR312  10_1%_6  [R0603]  148.32 37.53 0 bottom
PR313  10_1%_2  [R0201]  130.26 37.2 90 bottom
PR314  10_1%_2  [R0201]  127.44 36.05 90 bottom
PR315  *short_2  [S0201]  129.22 36.05 90 bottom
PR316  *short_2  [S0201]  129.98 36.05 90 bottom
PR317  *short_2  [S0201]  135.41 35.66 270 bottom
PR318  *short_2  [S0201]  143.57 35.55 270 bottom
PR319  4.02K_1%_4  [R0402]  133.62 35.06 90 bottom
PR320  4.02K_1%_4  [R0402]  134.58 35.06 90 bottom
PR321  866K_1%_4  [R0402]  136.25 35.06 90 bottom
PR322  *short_2  [S0201]  137.22 34.91 180 bottom
PR323  *short_2  [S0201]  137.76 33.86 180 bottom
PR324  *short_2  [S0201]  137.76 33.15 180 bottom
PR325  *short_2  [S0201]  137.76 31.95 180 bottom
PR326  150_5%_4  [R0402]  112.2 31.74 270 bottom
PR327  *short_2  [S0201]  137.76 31.24 180 bottom
PR328  5.1_1%_6  [R0603]  129.52 31.06 0 bottom
PR329  *short_2  [S0201]  155.38 26.68 180 bottom
PR330  *short_2  [S0201]  156.91 30.29 90 bottom
PR331  *4.7_5%_6  [R0603]  147.34 30.08 0 bottom
PR332  *10K_5%_4  [R0402]  138.21 30.02 180 bottom
PR333  *short_8  [S0805]  18.48 29.07 0 bottom
PR334  10K_5%_4  [R0402]  138.21 29.06 180 bottom
PR335  *short_2  [S0201]  151.7 28.94 180 bottom
PR336  10_1%_2  [R0201]  131.75 28.5 0 bottom
PR337  *short_2  [S0201]  136.28 28.36 270 bottom
PR338  *0_5%_2  [R0201]  136.99 28.36 270 bottom
PR339  10_1%_2  [R0201]  131.75 27.79 0 bottom
PR340  *4.7_5%_6  [R0603]  123.73 27.36 180 bottom
PR341  *short_8  [S0805]  18.48 27.04 180 bottom
PR342  *short_2  [S0201]  118.3 26.02 180 bottom
PR343  *short_2  [S0201]  118.3 25.26 180 bottom
PR344  0.01_1%_0612  [RC3216]  114.87 24.75 180 bottom
PR345  *4.7_5%_6  [R0603]  41.94 22.16 180 bottom
PR346  *10K_1%_4  [R0402]  45.09 16.04 0 bottom
PR347  10_1%_6  [R0603]  41.94 15.48 180 bottom
PR348  *Short_0201  [S0201]  41.21 14.21 0 bottom
PR349  *1K_1%_4  [R0402]  44.28 14.12 0 bottom
PR350  1K_1%_4  [R0402]  46 14.12 180 bottom
PR351  *short_2  [S0201]  47.43 14.08 180 bottom
PR352  4.7_5%_4  [R0402]  39.86 122.03 180 top
PU1  TPS51486RJER  [QFN18-3X3-5]  65.54 121.24 0 top
PU2  *EV@JW5213DFND_TRPBF  [DFN8-2X2-5-9P-MAX8902B]  88.33 114.29 270 top
PU3  RT3662AMGQW  [QFN40-5X5-4-41P-RT3662AC]  146.35 53.7 0 top
PU4  AOZ1331ADI  [DFN14-3X2-4-11P-0_8H]  154.91 28.76 180 top
PU5  AOZ1331ADI  [DFN14-3X2-4-11P-0_8H]  21.91 28.05 90 top
PU6  JW5222RSOTB_TRPBF  [SOT23-2_8-95-6P-1_1H]  195.26 27.42 270 top
PU7  JW5213DFND_TRPBF  [DFN8-2X2-5-9P-MAX8902B]  40.47 27.34 90 top
PU8  EV@RT3662AMGQW  [QFN40-5X5-4-41P-RT3662AC]  73.55 111.68 180 bottom
PU9  EV@UP8801SSW8  [SOP8-6-1_27-9P-G5795F11U]  111.82 85.46 270 bottom
PU10  EV@G5335QT2U  [QFN23-4X4-5-25P]  145.72 65.54 180 bottom
PU11  G5334CQT1U  [QFN23-4X4-5-25P]  142.97 42.74 270 bottom
PU12  TMP708AIDBVR  [SOT23-2_8-95-5P-LP2985-50DBVT]  112.28 35.7 90 bottom
PU13  RT6256BGQUF  [QFN12-3X3-45-0_6H]  145.29 32.74 270 bottom
PU14  BQ24780SRUYR  [QFN28-4X4-4-38P]  134.22 31.18 0 bottom
PU15  RT6258CGQUF  [QFN12-3X3-45-0_6H]  44 18.96 90 bottom
Q1  AO3413  [SOT23-2_38-95-3P]  52.79 112.05 270 top
Q2  DDTC144EUA-7-F  [SOT23-1_7-65-3P]  55.56 109.49 0 top
Q3  2N7002KDW  [SOT363-2_1-65-6P]  54.93 103.19 270 top
Q4  TSI@2N7002K  [SOT23-2-95-3P]  64.58 100.82 180 top
Q5  2N7002K  [SOT23-2-95-3P]  60.37 95.74 0 top
Q6  SSM6N43FU  [SC70-2_1-65-6P]  19.11 86.85 90 top
Q7  2N7002KDW  [SOT363-2_1-65-6P]  92.39 83.3 270 top
Q8  METR3904-G  [SOT23-2-95-3P]  100.7 83.07 270 top
Q9  2N7002K  [SOT23-2-95-3P]  97.22 82.28 0 top
Q10  2N7002K  [SOT23-2-95-3P]  106.11 81.39 270 top
Q11  METR3904-G  [SOT23-2-95-3P]  102.55 79.74 270 top
Q12  METR3904-G  [SOT23-2-95-3P]  104.84 76.31 270 top
Q13  2N7002K  [SOT23-2-95-3P]  106.56 72.88 270 top
Q14  *METR3904-G  [SOT23-2-95-3P]  111.69 44.49 90 top
Q15  PJA138K  [SOT23-2-95-3P]  150.56 38.59 180 top
Q16  2N7002K  [SOT23-2-95-3P]  103.31 34.28 0 top
Q17  EV@2N7002K  [SOT23-2-95-3P]  90.82 23.1 0 top
Q18  TPC@2N7002K  [SOT23-2-95-3P]  24.06 21.83 270 top
Q19  2N7002KDW  [SOT363-2_1-65-6P]  149.67 19.8 180 top
Q20  2N7002KDW  [SOT363-2_1-65-6P]  71.94 17.99 180 top
Q21  *ODD@AO3413  [SOT23-2_38-95-3P]  146.11 14.85 0 top
Q22  *ODD@2N7002K  [SOT23-2-95-3P]  149.79 12.94 270 top
Q23  *MS@AO3413  [SOT23-2_38-95-3P]  213.93 11.92 180 top
Q24  2N7002K  [SOT23-2-95-3P]  194.37 11.97 90 top
Q25  *MS@2N7002K  [SOT23-2-95-3P]  200.47 12.46 90 top
Q26  SSD@2N7002K  [SOT23-2-95-3P]  25.46 7.35 180 top
Q27  *SSD@AO3413  [SOT23-2_38-95-3P]  15.17 7.1 90 top
Q28  *SSD@2N7002K  [SOT23-2-95-3P]  28.89 5.57 0 top
Q29  EV@2N7002KDW  [SC70-2_1-65-6P]  108.01 124.07 0 bottom
Q30  METR3904-G  [SOT23-2-95-3P]  102.17 83.04 180 bottom
Q31  FDV301N  [SOT23-2-95-3P]  97.6 28.82 270 bottom
Q32  *2N7002K  [SOT23-2-95-3P]  68.51 25.26 180 bottom
Q33  *TPM@PJE138K  [SOT23-1_38-5-3P]  121.35 24.12 270 bottom
Q34  PBA@DMP2130L-7  [SOT23-2_38-95-3P]  51.6 21.2 0 bottom
Q35  2N7002K  [SOT23-2-95-3P]  160.97 20.56 270 top
Q36  METR3904-G  [SOT23-2-95-3P]  174.18 21.96 270 bottom
Q38  *PJA138K  [SOT23-2-95-3P]  196.78 20.31 90 bottom
Q39  FDV301N  [SOT23-2-95-3P]  207.83 19.29 270 bottom
Q40  KBL@DDTC144EUA-7-F  [SOT23-1_7-65-3P]  194.6 17.13 90 bottom
Q41  KBL@DMP2130L-7  [SOT23-2_38-95-3P]  197.42 14.72 90 bottom
Q42  **AOSS32334C  [SOT23-2_38-95-3P]  90.49 124.83 0 top
Q43  **AOSS32334C  [SOT23-2_38-95-3P]  80.58 123.28 0 top
Q44  *MS@2N7002KTB  [SOT23-1_38-5-3P]  179.39 21.45 270 bottom
R1  EV@10K_5%_2  [R0201]  119.95 125.46 0 top
R2  EV@4.7K_5%_2  [R0201]  118.65 125.08 90 top
R3  *EV@5.1K_1%_2  [R0201]  120.84 125.08 90 top
R4  *EV@5.1K/F_2  [R0201]  121.6 125.08 270 top
R5  *EV@5.1K/F_2  [R0201]  107.63 124.83 0 top
R6  EV@33_5%_2  [R0201]  108.65 124.83 0 top
R7  EV@33_5%_2  [R0201]  119.95 124.7 180 top
R8  EV@5.1K/F_2  [R0201]  108.65 124.07 180 top
R9  EV@4.7K_5%_2  [R0201]  118.65 123.66 270 top
R10  *EV@5.1K_1%_2  [R0201]  120.84 123.56 270 top
R11  EV@5.1K/F_2  [R0201]  121.6 123.56 270 top
R12  *EV@5.1K/F_2  [R0201]  122.49 123.56 270 top
R13  EV@5.1K/F_2  [R0201]  123.25 123.56 270 top
R14  EV@4.7K_5%_2  [R0201]  128.46 123.43 180 top
R15  *EV@0_5%_2  [R0201]  129.47 123.43 180 top
R16  EV@5.1K/F_2  [R0201]  107.63 123.18 0 top
R17  EV@33_5%_2  [R0201]  108.65 123.18 0 top
R18  *EV@0_5%_2  [R0201]  104.84 122.82 90 top
R19  EV@4.7K_5%_2  [R0201]  129.47 122.67 0 top
R20  EV@10K_5%_2  [R0201]  120.08 122.54 0 top
R21  EV@49.9_1%_2  [R0201]  124.52 122.54 90 top
R22  *EV@5.1K_1%_2  [R0201]  122.49 122.44 270 top
R23  *EV@5.1K_1%_2  [R0201]  123.25 122.44 90 top
R24  *EV@5.1K/F_2  [R0201]  108.65 122.41 180 top
R25  EV@33_5%_2  [R0201]  117.92 122.16 270 top
R26  EV@5.1K/F_2  [R0201]  120.97 122.03 270 top
R27  *EV@0_5%_2  [R0201]  105.6 121.91 90 top
R28  *EV@0_5%_2  [R0201]  128.33 121.91 0 top
R29  *EV@4.7K_5%_2  [R0201]  129.47 121.91 0 top
R30  EV@33_5%_2  [R0201]  120.08 121.78 180 top
R31  EV@4.7K_5%_2  [R0201]  125.66 121.53 0 top
R32  EV@33_5%_2  [R0201]  117.92 121.14 270 top
R33  *EV@Short_0201  [S0201]  128.33 121.14 180 top
R34  *EV@0_5%_2  [R0201]  129.47 121.14 180 top
R35  EV@5.1K/F_2  [R0201]  122.49 121.02 270 top
R36  *EV@4.7K_5%_2  [R0201]  125.66 120.76 180 top
R37  *EV@10K_5%_2  [R0201]  106.67 120.48 270 top
R38  *EV@5.1K/F_2  [R0201]  120.97 120.38 270 top
R39  *EV@10K_5%_2  [R0201]  123.63 120.26 0 top
R40  EV@10_1%_2  [R0201]  124.65 120.26 0 top
R41  *EV@5.1K/F_2  [R0201]  122.74 119.49 270 top
R42  EV@5.1K/F_2  [R0201]  124.65 119.49 180 top
R43  *EV@10K_5%_2  [R0201]  128.59 119.37 90 top
R44  EV@10K_5%_2  [R0201]  112.96 118.99 90 top
R45  EV@10K_5%_2  [R0201]  113.73 118.99 90 top
R46  EV@5.49K_1%_2  [R0201]  139.38 117.21 0 top
R47  EV@2.37K_1%_2  [R0201]  141.29 116.95 180 top
R48  EV@2.37K_1%_2  [R0201]  148.91 113.91 270 top
R49  EV@60.4_1%_2  [R0201]  142.17 113.4 180 top
R50  EV@5.49K_1%_2  [R0201]  148.98 113.02 180 top
R51  EV@60.4_1%_2  [R0201]  142.17 112.64 180 top
R52  *Short_0201  [S0201]  41.59 112.51 270 top
R53  *Short_0201  [S0201]  42.61 112.51 270 top
R54  *2.2_1%_8  [R0805]  49.34 112.51 0 top
R55  100K_5%_4  [R0402]  55.56 112.38 180 top
R56  10K_5%_4  [R0402]  55.56 113.4 0 top
R57  75_1%_8  [R0805]  31.68 111.62 90 top
R58  75_1%_8  [R0805]  28.76 111.52 90 top
R59  EV@1K_1%_2  [R0201]  143.33 111.38 0 top
R60  75_1%_8  [R0805]  34.73 111.37 90 top
R61  75_1%_8  [R0805]  37.53 111.37 90 top
R62  *100K_5%_4  [R0402]  55.56 111.37 180 top
R63  680_5%_4  [R0402]  44.64 109.84 270 top
R64  10_5%_4  [R0402]  45.65 109.84 90 top
R65  2.49K_1%_4  [R0402]  41.84 109.71 180 top
R66  *Short_0805  [S0805]  50.86 108.44 90 top
R67  100K_1%_4  [R0402]  60.77 108.19 270 top
R68  *1K_5%_2  [R0201]  56.65 107.63 0 top
R69  10_5%_4  [R0402]  57.72 107.56 90 top
R70  1K_1%_4  [R0402]  58.74 107.56 270 top
R71  *Short_0201  [S0201]  54.88 107.81 0 top
R72  *Short_0805  [S0805]  64.58 107.3 0 top
R73  *1K_5%_2  [R0201]  56.65 106.82 180 top
R74  *Short_0201  [S0201]  56.45 105.52 180 top
R75  *Short_0201  [S0201]  57.47 105.52 180 top
R76  10K_5%_4  [R0402]  53.86 105.12 0 top
R77  15K_1%_4  [R0402]  50.99 104.46 270 top
R78  1K_5%_2  [R0201]  49.97 104.58 180 top
R79  100K_5%_4  [R0402]  56.7 104.25 90 top
R80  TS@0_4  [R0402]  58.1 104.25 90 top
R81  *0_5%_6  [R0603]  59.75 104.13 270 top
R82  *Short_0603  [S0603]  61.78 104.13 270 top
R83  10K_5%_4  [R0402]  57.08 102.09 180 top
R84  TSI@100_5%_2  [R0201]  58.99 101.97 90 top
R85  TSI@10K_5%_2  [R0201]  60.77 101.84 270 top
R86  *TSI@10K_5%_2  [R0201]  61.53 101.84 270 top
R87  TSI@10K_5%_2  [R0201]  62.29 101.84 270 top
R88  EV@100_1%_2  [R0201]  118.04 101.33 90 top
R89  *EV@0.001_1%_1206  [R1206]  111.9 100.7 270 top
R90  EV@40.2_1%_2  [R0201]  118.04 100.32 90 top
R91  *10K_5%_4  [R0402]  53.91 100.19 270 top
R92  10K_5%_4  [R0402]  54.93 100.19 90 top
R93  DMIC@10K_5%_4  [R0402]  55.94 100.19 90 top
R94  *10K_5%_4  [R0402]  56.96 100.19 270 top
R95  EV@120_1%_4  [R0402]  118.63 98.69 270 top
R96  *EV@Short_0201  [S0201]  93.28 98.16 0 top
R97  *EV@Short_0201  [S0201]  94.42 98.16 0 top
R98  *EV@Short_0201  [S0201]  95.57 98.16 0 top
R99  *0_5%_4  [R0402]  59.37 98.03 180 top
R100  10K_5%_4  [R0402]  61.78 98.03 180 top
R101  EV@100_1%_2  [R0201]  114.11 97.78 180 top
R102  EV@40.2_1%_2  [R0201]  114.11 97.01 0 top
R103  EV@100K_5%_4  [R0402]  94.55 95.24 90 top
R104  39_1%_2  [R0201]  31.81 90.28 270 top
R105  39_1%_2  [R0201]  32.57 90.28 270 top
R106  39_1%_2  [R0201]  33.34 90.28 270 top
R107  39_1%_2  [R0201]  34.1 90.28 270 top
R108  39_1%_2  [R0201]  34.86 90.28 270 top
R109  39_1%_2  [R0201]  35.62 90.28 270 top
R110  39_1%_2  [R0201]  36.38 90.28 270 top
R111  39_1%_2  [R0201]  37.15 90.28 270 top
R112  39_1%_2  [R0201]  37.91 90.28 270 top
R113  39_1%_2  [R0201]  38.67 90.28 270 top
R114  39_1%_2  [R0201]  39.43 90.28 270 top
R115  *0_5%_2  [R0201]  30.54 89.52 180 top
R116  4.7K_5%_2  [R0201]  19.49 89.27 0 top
R117  39_1%_2  [R0201]  30.54 88.76 0 top
R118  39_1%_2  [R0201]  30.54 88 0 top
R119  39_1%_2  [R0201]  30.54 87.24 0 top
R120  EV@1K_1%_2  [R0201]  143.35 87.19 270 top
R121  2.2K_5%_2  [R0201]  14.54 87.11 90 top
R122  2.2K_5%_2  [R0201]  16.44 87.11 90 top
R123  39_1%_2  [R0201]  30.54 86.47 0 top
R124  39_1%_2  [R0201]  30.54 85.71 0 top
R125  EV@60.4_1%_2  [R0201]  142.17 85.33 180 top
R126  39_1%_2  [R0201]  30.54 84.95 0 top
R127  EV@60.4_1%_2  [R0201]  142.17 84.57 180 top
R128  4.7K_5%_2  [R0201]  96.2 84.49 180 top
R129  4.7K_5%_2  [R0201]  18.73 84.44 180 top
R130  39_1%_2  [R0201]  30.54 84.19 0 top
R131  1K_1%_2  [R0201]  90.74 83.68 270 top
R132  39_1%_2  [R0201]  30.54 83.43 0 top
R133  1K_1%_2  [R0201]  102.83 83.3 90 top
R134  39_1%_2  [R0201]  30.54 82.66 0 top
R135  1K_1%_2  [R0201]  90.74 82.66 90 top
R136  *4.7K_5%_2  [R0201]  20 82.51 0 top
R137  100K_5%_2  [R0201]  102.83 82.28 270 top
R138  10K_5%_2  [R0201]  24.06 82.03 90 top
R139  39_1%_2  [R0201]  30.54 81.9 0 top
R140  39_1%_2  [R0201]  29.91 81.14 0 top
R141  *Short_0201  [S0201]  24.19 81.14 180 top
R142  100K_5%_2  [R0201]  100.14 81.01 180 top
R143  6.2_1%_0201  [R0201]  17.71 80.58 0 top
R144  39_1%_2  [R0201]  30.54 80.38 0 top
R145  4.99K_1%_4  [R0402]  23.18 80.25 90 top
R146  6.2_1%_0201  [R0201]  17.71 79.84 0 top
R147  39_1%_2  [R0201]  30.54 79.62 0 top
R148  6.2_1%_0201  [R0201]  14.54 79.36 0 top
R149  6.2_1%_0201  [R0201]  17.71 79.11 0 top
R150  39_1%_2  [R0201]  40.32 78.98 180 top
R151  *G3@10K_5%_4  [R0402]  98.11 78.98 0 top
R152  240_1%_2  [R0201]  43.11 78.85 270 top
R153  SP@0_5%_2  [R0201]  37.78 78.78 180 top
R154  6.2_1%_0201  [R0201]  14.54 78.6 0 top
R155  6.2_1%_0201  [R0201]  17.71 78.35 0 top
R156  39_1%_2  [R0201]  40.32 78.22 180 top
R157  SP@0_5%_2  [R0201]  45.02 78.09 180 top
R158  G2@10K_5%_4  [R0402]  99.5 78.09 270 top
R159  SP@0_5%_2  [R0201]  37.78 78.04 0 top
R160  1K_1%_2  [R0201]  32.83 77.96 180 top
R161  SP@39_1%_2  [R0201]  33.84 77.96 0 top
R162  TSI_N@10K_5%_4  [R0402]  97.47 77.58 90 top
R163  TSI@10K_5%_4  [R0402]  98.49 77.58 270 top
R164  100K_5%_2  [R0201]  107 76.69 270 top
R165  4.7K_5%_2  [R0201]  21.65 76.4 90 top
R166  10K_5%_4  [R0402]  99.76 76.06 90 top
R167  *10K_5%_4  [R0402]  100.77 76.06 270 top
R168  *10K_5%_4  [R0402]  101.79 76.06 270 top
R169  0_4  [R0402]  15.43 75.81 180 top
R170  2.2K_5%_2  [R0201]  107 75.55 90 top
R171  0_4  [R0402]  15.43 74.79 180 top
R172  10K_5%_4  [R0402]  101.79 74.66 0 top
R173  *1K_1%_2  [R0201]  51.88 67.68 0 top
R174  SP@0_5%_2  [R0201]  36.64 67.3 180 top
R175  SP@0_5%_2  [R0201]  37.65 67.3 180 top
R176  240_1%_2  [R0201]  42.1 65.66 270 top
R177  SP@0_5%_2  [R0201]  42.94 65.66 90 top
R178  1K_1%_2  [R0201]  48.07 62.98 180 top
R179  *Short_0201  [S0201]  23.68 58.66 180 top
R180  *Short_0201  [S0201]  23.68 57.64 180 top
R181  *0_5%_6  [R0603]  50.35 56.63 90 top
R182  *Short_0603  [S0603]  85.78 55.24 0 top
R183  1K_1%_2  [R0201]  50.23 53.2 0 top
R184  TPC@0_5%_2  [R0201]  20.89 52.82 0 top
R185  TPC_N@0_5%_2  [R0201]  21.34 52.82 180 top
R186  1K_1%_2  [R0201]  51.62 52.18 0 top
R187  TPC@0_5%_2  [R0201]  20.89 51.55 0 top
R188  TPC_N@0_5%_2  [R0201]  21.34 51.55 180 top
R189  *150_1%_2  [R0201]  118.04 50.66 270 top
R190  TPC@10K_5%_4  [R0402]  23.94 50.68 0 top
R191  *1K_1%_2  [R0201]  118.04 49.64 90 top
R192  TPC@39K_1%_4  [R0402]  16.52 49.01 90 top
R193  TPC@10K_5%_4  [R0402]  24.32 48.88 0 top
